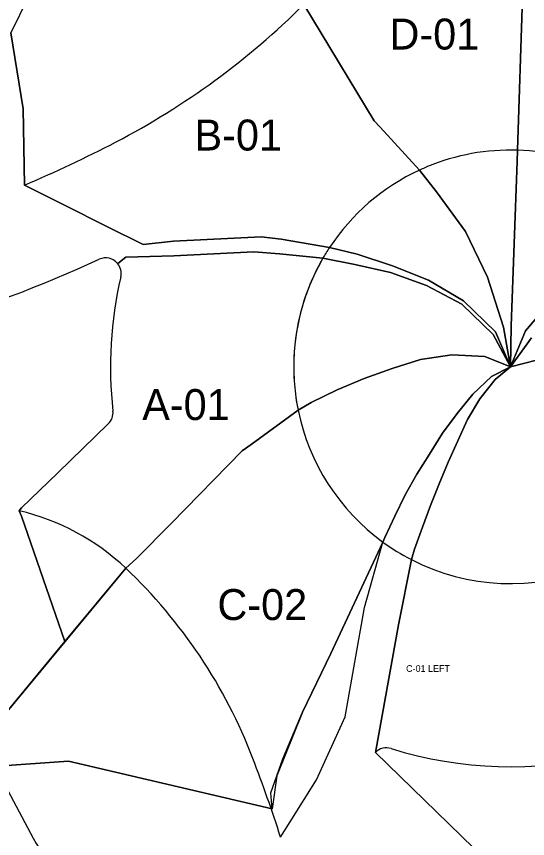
# Model space of a CAD drawing. Extents: x 5196716 to 5200291, y 3709146 to 3713154.
# Drawn here: x 5196805.6 to 5196904.7, y 3709265.9 to 3709425.2 of the extents above; entities that cross this region are included whole.
import ezdxf

# ---------------------------------------------------------------- set-up
doc = ezdxf.new("R2010")
doc.units = 0
for name, color, linetype in [('dsnTextNote', 7, 'Continuous'), ('Level 1', 7, 'Continuous'), ('Level 2', 7, 'Continuous'), ('Level 4', 7, 'Continuous')]:
    doc.layers.add(name, color=color, linetype=linetype)

msp = doc.modelspace()

# ---------------------------------------------------------------- linework, layer by layer
at = {"layer": 'Level 1'}
for p, q in [((5196815.9, 3709445.18), (5196804.52, 3709421.99)), ((5196903.91, 3709434.75), (5196902.74, 3709399.27)), ((5196902.74, 3709399.27), (5196903.91, 3709434.75)), ((5196903.91, 3709434.75), (5196902.74, 3709399.27)), ((5196874.95, 3709404.96), (5196861.31, 3709427.51)), ((5196861.31, 3709427.51), (5196874.95, 3709404.96)), ((5196876.11, 3709403.76), (5196874.95, 3709404.96)), ((5196874.95, 3709404.96), (5196876.11, 3709403.76)), ((5196883.71, 3709395.4), (5196876.11, 3709403.76)), ((5196876.11, 3709403.76), (5196883.71, 3709395.4)), ((5196902.74, 3709399.27), (5196902.66, 3709397.09)), ((5196902.66, 3709397.09), (5196902.74, 3709399.27)), ((5196902.74, 3709399.27), (5196902.66, 3709397.09)), ((5196902.66, 3709397.09), (5196902.26, 3709386.47)), ((5196902.26, 3709386.47), (5196902.66, 3709397.09)), ((5196902.66, 3709397.09), (5196902.26, 3709386.47)), ((5196887.04, 3709391.23), (5196883.71, 3709395.4)), ((5196883.71, 3709395.4), (5196887.04, 3709391.23)), ((5196807.21, 3709392.52), (5196814.67, 3709388.78)), ((5196814.67, 3709388.78), (5196807.21, 3709392.52)), ((5196892.64, 3709383.55), (5196887.04, 3709391.23)), ((5196887.04, 3709391.23), (5196892.64, 3709383.55)), ((5196814.67, 3709388.78), (5196823.44, 3709384.39)), ((5196823.44, 3709384.39), (5196814.67, 3709388.78)), ((5196902.26, 3709386.47), (5196901.86, 3709375.85)), ((5196901.86, 3709375.85), (5196902.26, 3709386.47)), ((5196902.26, 3709386.47), (5196901.86, 3709375.85)), ((5196823.44, 3709384.39), (5196830.21, 3709381.01)), ((5196830.21, 3709381.01), (5196823.44, 3709384.39)), ((5196896.92, 3709374.66), (5196892.64, 3709383.55)), ((5196892.64, 3709383.55), (5196896.92, 3709374.66)), ((5196836.14, 3709378.82), (5196851.63, 3709379.6)), ((5196851.63, 3709379.6), (5196856.62, 3709379.17)), ((5196856.62, 3709379.17), (5196865.01, 3709378.32)), ((5196826.83, 3709378.53), (5196825.27, 3709377.29)), ((5196825.27, 3709377.29), (5196826.83, 3709378.53)), ((5196826.83, 3709378.53), (5196836.14, 3709378.82)), ((5196901.86, 3709375.85), (5196901.47, 3709365.23)), ((5196901.47, 3709365.23), (5196901.86, 3709375.85)), ((5196901.86, 3709375.85), (5196901.47, 3709365.23)), ((5196899.99, 3709364.96), (5196896.92, 3709374.66)), ((5196896.92, 3709374.66), (5196899.99, 3709364.96)), ((5196901.36, 3709357.29), (5196899.99, 3709364.96)), ((5196899.99, 3709364.96), (5196901.36, 3709357.29)), ((5196901.47, 3709365.23), (5196901.36, 3709357.29)), ((5196901.36, 3709357.29), (5196901.47, 3709365.23)), ((5196901.47, 3709365.23), (5196901.36, 3709357.29)), ((5196905.44, 3709362.91), (5196901.36, 3709357.29)), ((5196901.36, 3709357.29), (5196905.44, 3709362.91)), ((5196901.36, 3709357.29), (5196906.42, 3709358.57)), ((5196906.42, 3709358.57), (5196901.36, 3709357.29)), ((5196901.36, 3709357.29), (5196898.37, 3709354.84)), ((5196898.37, 3709354.84), (5196901.36, 3709357.29)), ((5196898.37, 3709354.84), (5196895.4, 3709351.11)), ((5196895.4, 3709351.11), (5196898.37, 3709354.84)), ((5196895.4, 3709351.11), (5196893.01, 3709347.11)), ((5196893.01, 3709347.11), (5196895.4, 3709351.11)), ((5196860.21, 3709348.88), (5196851.12, 3709342.25)), ((5196893.01, 3709347.11), (5196891.14, 3709342.94)), ((5196891.14, 3709342.94), (5196893.01, 3709347.11)), ((5196823.44, 3709346.23), (5196813.66, 3709336.74)), ((5196813.66, 3709336.74), (5196823.44, 3709346.23)), ((5196891.14, 3709342.94), (5196889.27, 3709338.79)), ((5196889.27, 3709338.79), (5196891.14, 3709342.94)), ((5196851.12, 3709342.25), (5196849.35, 3709340.99)), ((5196889.27, 3709338.79), (5196887.53, 3709334.61)), ((5196887.53, 3709334.61), (5196889.27, 3709338.79)), ((5196813.66, 3709336.74), (5196806.6, 3709329.99)), ((5196806.6, 3709329.99), (5196813.66, 3709336.74)), ((5196887.53, 3709334.61), (5196885.88, 3709330.41)), ((5196885.88, 3709330.41), (5196887.53, 3709334.61)), ((5196806.6, 3709329.99), (5196806.15, 3709329.4)), ((5196806.15, 3709329.4), (5196806.6, 3709329.99)), ((5196885.88, 3709330.41), (5196884.31, 3709326.2)), ((5196884.31, 3709326.2), (5196885.88, 3709330.41)), ((5196884.31, 3709326.2), (5196882.8, 3709321.96)), ((5196882.8, 3709321.96), (5196884.31, 3709326.2)), ((5196866.57, 3709301.75), (5196876.63, 3709323.34)), ((5196876.63, 3709323.34), (5196871.6, 3709312.55)), ((5196882.8, 3709321.96), (5196882.16, 3709319.94)), ((5196882.16, 3709319.94), (5196882.8, 3709321.96)), ((5196828.88, 3709320.15), (5196826.8, 3709318.28)), ((5196882.16, 3709319.94), (5196879.7, 3709307.28)), ((5196879.7, 3709307.28), (5196882.16, 3709319.94)), ((5196826.8, 3709318.28), (5196798.89, 3709284.57)), ((5196879.7, 3709307.28), (5196875.18, 3709282.55)), ((5196875.18, 3709282.55), (5196879.7, 3709307.28)), ((5196798.89, 3709284.57), (5196815.03, 3709304.07)), ((5196866.57, 3709301.75), (5196861.06, 3709290.4)), ((5196861.06, 3709290.4), (5196856.07, 3709278.03)), ((5196857.24, 3709281.34), (5196861.06, 3709290.4)), ((5196875.18, 3709282.55), (5196894.21, 3709264.09)), ((5196894.21, 3709264.09), (5196875.18, 3709282.55)), ((5196801.4, 3709279.88), (5196815.75, 3709280.89)), ((5196815.75, 3709280.89), (5196801.4, 3709279.88)), ((5196815.75, 3709280.89), (5196855.22, 3709271.64)), ((5196855.17, 3709271.61), (5196815.75, 3709280.89)), ((5196854.9, 3709274.72), (5196857.24, 3709281.34)), ((5196802.22, 3709278.35), (5196808.33, 3709266.93)), ((5196856.07, 3709278.03), (5196855.17, 3709271.61)), ((5196855.22, 3709271.64), (5196854.9, 3709274.72))]:
    msp.add_line(p, q, dxfattribs=at)
for points in [[(5196804.52, 3709421.99), (5196806.95, 3709407.32), (5196807.21, 3709392.52)], [(5196807.21, 3709392.52), (5196806.95, 3709407.32), (5196804.52, 3709421.99)], [(5196830.21, 3709381.01), (5196836.06, 3709381.64), (5196853.04, 3709382.5)], [(5196853.04, 3709382.5), (5196836.06, 3709381.64), (5196830.21, 3709381.01)], [(5196853.04, 3709382.5), (5196856.95, 3709382.06), (5196866.28, 3709380.39)], [(5196866.28, 3709380.39), (5196856.95, 3709382.06), (5196853.04, 3709382.5)], [(5196934.43, 3709383.18), (5196931.47, 3709382.38), (5196924.29, 3709379.72), (5196917.18, 3709376.21), (5196910.26, 3709371.32), (5196904.27, 3709364.25), (5196901.36, 3709357.29)], [(5196901.36, 3709357.29), (5196904.27, 3709364.25), (5196910.26, 3709371.32), (5196917.18, 3709376.21), (5196924.29, 3709379.72), (5196931.47, 3709382.38), (5196934.43, 3709383.18)], [(5196865.01, 3709378.32), (5196856.62, 3709379.17), (5196851.63, 3709379.6), (5196836.14, 3709378.82), (5196826.83, 3709378.53)], [(5196866.28, 3709380.39), (5196871.63, 3709379.15), (5196878.52, 3709376.89), (5196885.48, 3709374.07), (5196892.27, 3709370.09), (5196898.49, 3709364.07), (5196901.36, 3709357.29)], [(5196901.36, 3709357.29), (5196898.49, 3709364.07), (5196892.27, 3709370.09), (5196885.48, 3709374.07), (5196878.52, 3709376.89), (5196871.63, 3709379.15), (5196866.28, 3709380.39)], [(5196901.36, 3709357.29), (5196898, 3709363.56), (5196891.92, 3709369.45), (5196885.09, 3709373.08), (5196878.11, 3709375.55), (5196871.19, 3709377.15), (5196865.01, 3709378.32)], [(5196865.01, 3709378.32), (5196871.19, 3709377.15), (5196878.11, 3709375.55), (5196885.09, 3709373.08), (5196891.92, 3709369.45), (5196898, 3709363.56), (5196901.36, 3709357.29)], [(5196860.21, 3709348.88), (5196862.76, 3709350.37), (5196867.81, 3709352.82), (5196872.99, 3709355.05), (5196878.41, 3709356.94), (5196883.96, 3709358.72), (5196890.02, 3709359.6), (5196896.42, 3709359.32), (5196901.36, 3709357.29)], [(5196901.36, 3709357.29), (5196896.42, 3709359.32), (5196890.02, 3709359.6), (5196883.96, 3709358.72), (5196878.41, 3709356.94), (5196872.99, 3709355.05), (5196867.81, 3709352.82), (5196862.76, 3709350.37), (5196860.21, 3709348.88)], [(5196876.63, 3709323.34), (5196877.02, 3709324.21), (5196878.96, 3709328.35), (5196880.98, 3709332.47), (5196883.19, 3709336.52), (5196885.68, 3709340.38), (5196888.18, 3709344.44), (5196891.04, 3709348.22), (5196894.07, 3709352.02), (5196897.72, 3709355.44), (5196901.36, 3709357.29)], [(5196901.36, 3709357.29), (5196897.72, 3709355.44), (5196894.07, 3709352.02), (5196891.04, 3709348.22), (5196888.18, 3709344.44), (5196885.68, 3709340.38), (5196883.19, 3709336.52), (5196880.98, 3709332.47), (5196878.96, 3709328.35), (5196877.02, 3709324.21), (5196876.63, 3709323.34)], [(5196815.03, 3709304.07), (5196826.8, 3709318.28), (5196828.88, 3709320.15), (5196835.64, 3709326.95), (5196849.35, 3709340.99), (5196851.12, 3709342.25), (5196860.21, 3709348.88)], [(5196849.35, 3709340.99), (5196835.64, 3709326.95), (5196828.88, 3709320.15)], [(5196806.15, 3709329.4), (5196806.63, 3709328.38), (5196815.03, 3709304.07)], [(5196815.03, 3709304.07), (5196806.63, 3709328.38), (5196806.15, 3709329.4)], [(5196871.6, 3709312.55), (5196866.57, 3709301.75)], [(5196861.06, 3709290.4), (5196866.57, 3709301.75)]]:
    msp.add_lwpolyline(points, dxfattribs=at)
for centre, radius, start, end in [((5196710.5, 3709620.34), 266.5, 278.646, 294.6564), ((5196710.5, 3709620.34), 266.5, 278.646, 294.6564), ((5196822.93, 3709375.41), 3, 38.6525, 114.6564), ((5196822.93, 3709375.41), 3, 38.6525, 114.6564), ((5196822.93, 3709375.41), 3, 346.9887, 38.6525), ((5196822.93, 3709375.41), 3, 346.9887, 38.6525), ((5196901.36, 3709357.29), 77.5, 166.9887, 186.35), ((5196901.36, 3709357.29), 77.5, 166.9887, 186.35), ((5196821.35, 3709348.39), 3, 314.1428, 6.35), ((5196821.35, 3709348.39), 3, 314.1428, 6.35), ((5196845.36, 3709286.76), 42, 208.1667, 257.8923)]:
    msp.add_arc(centre, radius, start, end, dxfattribs=at)
at = {"layer": 'Level 2'}
for p, q in [((5196902.74, 3709399.27), (5196903.91, 3709434.75)), ((5196903.91, 3709434.75), (5196902.74, 3709399.27)), ((5196861.31, 3709427.51), (5196874.95, 3709404.96)), ((5196874.95, 3709404.96), (5196861.31, 3709427.51)), ((5196874.95, 3709404.96), (5196876.11, 3709403.76)), ((5196876.11, 3709403.76), (5196874.95, 3709404.96)), ((5196876.11, 3709403.76), (5196883.71, 3709395.4)), ((5196883.71, 3709395.4), (5196876.11, 3709403.76)), ((5196807.21, 3709392.52), (5196814.67, 3709388.78)), ((5196814.67, 3709388.78), (5196823.44, 3709384.39)), ((5196823.44, 3709384.39), (5196830.21, 3709381.01)), ((5196836.06, 3709381.64), (5196853.04, 3709382.5)), ((5196853.04, 3709382.5), (5196856.95, 3709382.06)), ((5196830.21, 3709381.01), (5196836.06, 3709381.64)), ((5196856.95, 3709382.06), (5196866.28, 3709380.39)), ((5196865.01, 3709378.32), (5196856.62, 3709379.17)), ((5196826.83, 3709378.53), (5196825.27, 3709377.29)), ((5196836.14, 3709378.82), (5196826.83, 3709378.53)), ((5196851.12, 3709342.25), (5196860.21, 3709348.88)), ((5196860.21, 3709348.88), (5196851.12, 3709342.25)), ((5196823.44, 3709346.23), (5196813.66, 3709336.74)), ((5196835.64, 3709326.95), (5196849.35, 3709340.99)), ((5196849.35, 3709340.99), (5196835.64, 3709326.95)), ((5196849.35, 3709340.99), (5196851.12, 3709342.25)), ((5196851.12, 3709342.25), (5196849.35, 3709340.99)), ((5196813.66, 3709336.74), (5196806.6, 3709329.99)), ((5196806.6, 3709329.99), (5196806.15, 3709329.4)), ((5196828.88, 3709320.15), (5196835.64, 3709326.95)), ((5196835.64, 3709326.95), (5196828.88, 3709320.15)), ((5196873.11, 3709310.68), (5196876.63, 3709323.34)), ((5196826.8, 3709318.28), (5196828.88, 3709320.15)), ((5196828.88, 3709320.15), (5196826.8, 3709318.28)), ((5196882.16, 3709319.94), (5196879.7, 3709307.28)), ((5196879.7, 3709307.28), (5196875.18, 3709282.55)), ((5196863.77, 3709277.28), (5196869.36, 3709289.46)), ((5196858.67, 3709269.11), (5196863.77, 3709277.28)), ((5196856.81, 3709266.15), (5196858.67, 3709269.11))]:
    msp.add_line(p, q, dxfattribs=at)
for points in [[(5196856.62, 3709379.17), (5196851.63, 3709379.6), (5196836.14, 3709378.82)], [(5196869.36, 3709289.46), (5196873.11, 3709310.68)]]:
    msp.add_lwpolyline(points, dxfattribs=at)
for centre, radius, start, end in [((5196901.36, 3709357.29), 77.5, 38.2026, 88.1128), ((5196755.55, 3709533.87), 150, 297.5187, 314.8402), ((5196710.5, 3709620.34), 247.5, 293.0025, 297.5187), ((5196901.36, 3709357.29), 42, 88.1128, 112.5062), ((5196901.36, 3709357.29), 42, 38.0641, 88.1128), ((5196901.36, 3709357.29), 42, 114.8473, 146.6296), ((5196901.36, 3709357.29), 42, 112.5062, 114.8473), ((5196901.36, 3709357.29), 42, 149.9459, 163.7438), ((5196822.93, 3709375.41), 3, 346.9887, 38.6525), ((5196901.36, 3709357.29), 77.5, 166.9887, 186.35), ((5196901.36, 3709357.29), 42, 163.7438, 191.5567), ((5196821.35, 3709348.39), 3, 314.1428, 6.35), ((5196901.36, 3709357.29), 42, 191.5567, 233.9331), ((5196901.36, 3709357.29), 42, 242.7935, 341.6137), ((5196795.87, 3709285.59), 45, 46.5753, 76.7934), ((5196758.06, 3709245.65), 100, 20.9281, 46.5753), ((5196901.36, 3709357.29), 77.5, 252.6379, 314.4832), ((5196877.34, 3709280.46), 3, 72.6379, 135.8835), ((5196573.59, 3709175.1), 297.5, 17.8218, 20.9281)]:
    msp.add_arc(centre, radius, start, end, dxfattribs=at)
at = {"layer": 'Level 4'}
for p, q in [((5196902.66, 3709397.09), (5196902.74, 3709399.27)), ((5196902.74, 3709399.27), (5196902.66, 3709397.09)), ((5196902.26, 3709386.47), (5196902.66, 3709397.09)), ((5196902.66, 3709397.09), (5196902.26, 3709386.47)), ((5196883.71, 3709395.4), (5196887.04, 3709391.23)), ((5196887.04, 3709391.23), (5196883.71, 3709395.4)), ((5196887.04, 3709391.23), (5196892.64, 3709383.55)), ((5196892.64, 3709383.55), (5196887.04, 3709391.23)), ((5196901.86, 3709375.85), (5196902.26, 3709386.47)), ((5196902.26, 3709386.47), (5196901.86, 3709375.85)), ((5196892.64, 3709383.55), (5196896.92, 3709374.66)), ((5196896.92, 3709374.66), (5196892.64, 3709383.55)), ((5196871.63, 3709379.15), (5196866.28, 3709380.39)), ((5196878.52, 3709376.89), (5196871.63, 3709379.15)), ((5196865.01, 3709378.32), (5196871.19, 3709377.15)), ((5196885.48, 3709374.07), (5196878.52, 3709376.89)), ((5196901.47, 3709365.23), (5196901.86, 3709375.85)), ((5196901.86, 3709375.85), (5196901.47, 3709365.23)), ((5196896.92, 3709374.66), (5196899.99, 3709364.96)), ((5196899.99, 3709364.96), (5196896.92, 3709374.66)), ((5196892.27, 3709370.09), (5196885.48, 3709374.07)), ((5196898.49, 3709364.07), (5196892.27, 3709370.09)), ((5196899.99, 3709364.96), (5196901.36, 3709357.29)), ((5196901.36, 3709357.29), (5196899.99, 3709364.96)), ((5196901.36, 3709357.29), (5196901.47, 3709365.23)), ((5196901.47, 3709365.23), (5196901.36, 3709357.29)), ((5196901.36, 3709357.29), (5196898.49, 3709364.07)), ((5196905.44, 3709362.91), (5196901.36, 3709357.29)), ((5196901.36, 3709357.29), (5196905.44, 3709362.91)), ((5196883.96, 3709358.72), (5196878.41, 3709356.94)), ((5196890.02, 3709359.6), (5196883.96, 3709358.72)), ((5196896.42, 3709359.32), (5196890.02, 3709359.6)), ((5196901.36, 3709357.29), (5196896.42, 3709359.32)), ((5196906.42, 3709358.57), (5196901.36, 3709357.29)), ((5196901.36, 3709357.29), (5196906.42, 3709358.57)), ((5196878.41, 3709356.94), (5196872.99, 3709355.05)), ((5196901.36, 3709357.29), (5196897.72, 3709355.44)), ((5196898.37, 3709354.84), (5196901.36, 3709357.29)), ((5196901.36, 3709357.29), (5196898.37, 3709354.84)), ((5196872.99, 3709355.05), (5196867.81, 3709352.82)), ((5196895.4, 3709351.11), (5196898.37, 3709354.84)), ((5196898.37, 3709354.84), (5196895.4, 3709351.11)), ((5196867.81, 3709352.82), (5196862.76, 3709350.37)), ((5196862.76, 3709350.37), (5196860.21, 3709348.88)), ((5196893.01, 3709347.11), (5196895.4, 3709351.11)), ((5196895.4, 3709351.11), (5196893.01, 3709347.11)), ((5196891.04, 3709348.22), (5196888.18, 3709344.44)), ((5196891.14, 3709342.94), (5196893.01, 3709347.11)), ((5196893.01, 3709347.11), (5196891.14, 3709342.94)), ((5196889.27, 3709338.79), (5196891.14, 3709342.94)), ((5196891.14, 3709342.94), (5196889.27, 3709338.79)), ((5196887.53, 3709334.61), (5196889.27, 3709338.79)), ((5196889.27, 3709338.79), (5196887.53, 3709334.61)), ((5196883.19, 3709336.52), (5196880.98, 3709332.47)), ((5196885.88, 3709330.41), (5196887.53, 3709334.61)), ((5196887.53, 3709334.61), (5196885.88, 3709330.41)), ((5196880.98, 3709332.47), (5196878.96, 3709328.35)), ((5196884.31, 3709326.2), (5196885.88, 3709330.41)), ((5196885.88, 3709330.41), (5196884.31, 3709326.2)), ((5196882.8, 3709321.96), (5196884.31, 3709326.2)), ((5196884.31, 3709326.2), (5196882.8, 3709321.96)), ((5196882.16, 3709319.94), (5196882.8, 3709321.96)), ((5196882.8, 3709321.96), (5196882.16, 3709319.94))]:
    msp.add_line(p, q, dxfattribs=at)
for points in [[(5196901.36, 3709357.29), (5196904.27, 3709364.25), (5196910.26, 3709371.32), (5196917.18, 3709376.21), (5196924.29, 3709379.72), (5196931.47, 3709382.38), (5196934.43, 3709383.18)], [(5196866.28, 3709380.39), (5196871.63, 3709379.15), (5196878.52, 3709376.89), (5196885.48, 3709374.07), (5196892.27, 3709370.09), (5196898.49, 3709364.07), (5196901.36, 3709357.29)], [(5196924.29, 3709379.72), (5196917.18, 3709376.21), (5196910.26, 3709371.32), (5196904.27, 3709364.25), (5196901.36, 3709357.29)], [(5196901.36, 3709357.29), (5196898, 3709363.56), (5196891.92, 3709369.45), (5196885.09, 3709373.08), (5196878.11, 3709375.55), (5196871.19, 3709377.15), (5196865.01, 3709378.32)], [(5196871.19, 3709377.15), (5196878.11, 3709375.55), (5196885.09, 3709373.08)], [(5196885.09, 3709373.08), (5196891.92, 3709369.45), (5196898, 3709363.56), (5196901.36, 3709357.29)], [(5196860.21, 3709348.88), (5196862.76, 3709350.37), (5196867.81, 3709352.82), (5196872.99, 3709355.05), (5196878.41, 3709356.94), (5196883.96, 3709358.72), (5196890.02, 3709359.6), (5196896.42, 3709359.32), (5196901.36, 3709357.29)], [(5196876.63, 3709323.34), (5196877.02, 3709324.21), (5196878.96, 3709328.35), (5196880.98, 3709332.47), (5196883.19, 3709336.52), (5196885.68, 3709340.38), (5196888.18, 3709344.44), (5196891.04, 3709348.22), (5196894.07, 3709352.02), (5196897.72, 3709355.44), (5196901.36, 3709357.29)], [(5196897.72, 3709355.44), (5196894.07, 3709352.02), (5196891.04, 3709348.22)], [(5196888.18, 3709344.44), (5196885.68, 3709340.38), (5196883.19, 3709336.52)], [(5196878.96, 3709328.35), (5196877.02, 3709324.21), (5196876.63, 3709323.34)]]:
    msp.add_lwpolyline(points, dxfattribs=at)
for start, end in [(88.1128, 112.5062), (38.0641, 88.1128), (114.8473, 146.6296), (112.5062, 114.8473), (146.6296, 149.9459), (149.9459, 191.5567), (191.5567, 233.9331), (242.7935, 341.6137), (233.9331, 242.7935)]:
    msp.add_arc((5196901.36, 3709357.29), 42, start, end, dxfattribs=at)

# ---------------------------------------------------------------- texts
at = {"layer": 'dsnTextNote'}
for s, height, p in [('D-01', 6, (5196877.92, 3709418.78)), ('B-01', 6, (5196840.14, 3709399.21)), ('A-01', 6, (5196830.01, 3709346.98)), ('C-02', 6, (5196844.58, 3709308.22)), ('C-01 LEFT', 1.3, (5196881.14, 3709298.18))]:
    msp.add_text(s, height=height, dxfattribs=at).set_placement(p)

doc.saveas('drawing.dxf')
